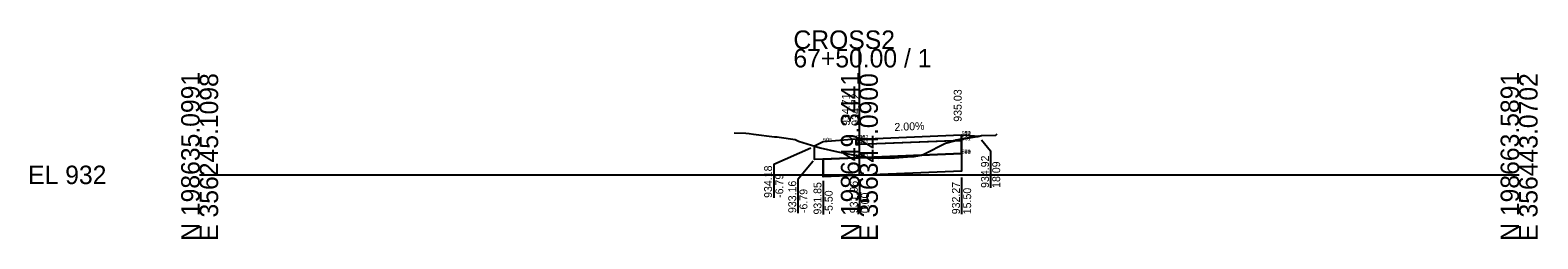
# Model space of a CAD drawing. Extents: x -26 to 203, y -10 to 14021.
# Drawn here: x -25.7 to 202.8, y 8490.3 to 8521.9 of the extents above; entities that cross this region are included whole.
import ezdxf

# ---------------------------------------------------------------- set-up
doc = ezdxf.new("R2010")
doc.units = 0
for name, color, linetype in [('Default', 7, 'Continuous'), ('P_E_XS_Ground', 7, 'Continuous'), ('P_XS', 7, 'Continuous'), ('P_XS_Bold', 7, 'Continuous'), ('P_XS_EAR_CommonGrnd', 7, 'Continuous'), ('P_XS_Lane', 7, 'Continuous'), ('P_XS_Rock', 7, 'Continuous')]:
    doc.layers.add(name, color=color, linetype=linetype)

msp = doc.modelspace()

# ---------------------------------------------------------------- linework, layer by layer
at = {"layer": 'Default'}
for p, q in [((100, 8500), (100, 8519.08)), ((0, 8500), (100, 8500)), ((100, 8500), (200, 8500))]:
    msp.add_line(p, q, dxfattribs=at)
at = {"layer": 'P_E_XS_Ground'}
for p, q in [((81.01, 8506.36), (82.8, 8506.3)), ((82.8, 8506.3), (83.28, 8506.29)), ((83.28, 8506.29), (83.94, 8506.16)), ((83.94, 8506.16), (87.15, 8505.77)), ((118.53, 8505.98), (120.68, 8506)), ((120.68, 8506), (120.89, 8506.23)), ((87.15, 8505.77), (87.53, 8505.74)), ((87.53, 8505.74), (87.86, 8505.71)), ((87.86, 8505.71), (90.25, 8505.35)), ((90.25, 8505.35), (90.77, 8505.13)), ((90.77, 8505.13), (94.07, 8504.09)), ((94.07, 8504.09), (96.71, 8503.5)), ((109.89, 8503.19), (113.07, 8504.79)), ((113.07, 8504.79), (114.63, 8505.24)), ((114.63, 8505.24), (117.57, 8505.75)), ((117.57, 8505.75), (117.94, 8505.8)), ((117.94, 8505.8), (118.53, 8505.98)), ((96.71, 8503.5), (100, 8502.85)), ((100, 8502.85), (100.9, 8502.66)), ((100.9, 8502.66), (101.25, 8502.6)), ((101.25, 8502.6), (102.92, 8502.55)), ((102.92, 8502.55), (105.3, 8502.58)), ((105.3, 8502.58), (107.95, 8502.76)), ((107.95, 8502.76), (108.31, 8502.78)), ((108.31, 8502.78), (109.43, 8502.97)), ((109.43, 8502.97), (109.89, 8503.19))]:
    msp.add_line(p, q, dxfattribs=at)
at = {"layer": 'P_XS'}
for p, q in [((115.5, 8506.05), (115.5, 8505.22)), ((93.21, 8502.33), (93.21, 8504.37)), ((99.5, 8505.41), (99.5, 8504.58)), ((99.5, 8504.58), (100, 8504.6)), ((115.5, 8505.22), (100, 8504.6)), ((115.5, 8503.22), (115.5, 8505.22)), ((99.5, 8502.58), (93.21, 8502.33)), ((94.5, 8502.38), (94.5, 8499.71)), ((99.5, 8502.58), (100, 8502.6)), ((115.5, 8503.22), (100, 8502.6)), ((115.5, 8503.22), (115.5, 8500.55)), ((115.5, 8500.55), (94.5, 8499.71))]:
    msp.add_line(p, q, dxfattribs=at)
at = {"layer": 'P_XS_EAR_CommonGrnd'}
for points in [[(100, 8505.43), (115.5, 8506.05), (115.5, 8505.39), (114.63, 8505.24), (114.4, 8505.17), (100, 8504.6), (99.5, 8504.58), (99.5, 8505.41)], [(115.5, 8506.05), (118.09, 8505.84), (117.94, 8505.8), (117.57, 8505.75), (115.5, 8505.39)], [(96.71, 8503.5), (100, 8502.85), (100.9, 8502.66), (101.02, 8502.64), (109.43, 8502.97), (109.89, 8503.19), (113.07, 8504.79), (114.4, 8505.17), (100, 8504.6), (99.5, 8504.58), (99.5, 8505.41), (94.5, 8505.01), (93.21, 8504.37), (94.07, 8504.09)], [(96.71, 8503.5), (100, 8502.85), (100.9, 8502.66), (101.02, 8502.64), (100, 8502.6), (99.5, 8502.58), (94.5, 8502.38), (93.21, 8502.33), (93.21, 8504.37), (94.07, 8504.09)], [(115.5, 8503.22), (109.43, 8502.97), (109.89, 8503.19), (113.07, 8504.79), (114.4, 8505.17), (115.5, 8505.22)], [(115.5, 8505.22), (114.4, 8505.17), (114.63, 8505.24), (115.5, 8505.39)], [(115.5, 8503.22), (115.5, 8500.55), (94.5, 8499.71), (94.5, 8502.38), (99.5, 8502.58), (100, 8502.6), (101.02, 8502.64), (101.25, 8502.6), (102.92, 8502.55), (105.3, 8502.58), (107.95, 8502.76), (108.31, 8502.78), (109.43, 8502.97)], [(109.43, 8502.97), (101.02, 8502.64), (101.25, 8502.6), (102.92, 8502.55), (105.3, 8502.58), (107.95, 8502.76), (108.31, 8502.78)]]:
    msp.add_lwpolyline(points, close=True, dxfattribs=at)
at = {"layer": 'P_XS_Lane'}
for p, q in [((100, 8505.43), (115.5, 8506.05)), ((115.5, 8506.05), (118.09, 8505.84)), ((94.5, 8505.01), (93.21, 8504.37)), ((99.5, 8505.41), (94.5, 8505.01)), ((99.5, 8505.41), (100, 8505.43))]:
    msp.add_line(p, q, dxfattribs=at)
at = {"layer": 'P_XS_Rock'}
for p, q in [((87.01, 8501.61), (92.66, 8504.12)), ((118.52, 8505.31), (119.89, 8503.63)), ((87.01, 8501.61), (87.01, 8496.51)), ((93.01, 8502.09), (90.67, 8499.31)), ((119.89, 8503.63), (119.89, 8498.01)), ((90.67, 8499.31), (90.67, 8494.21)), ((100, 8499.31), (100, 8494.19)), ((115.49, 8499.62), (115.49, 8494.03)), ((94.5, 8499.1), (94.5, 8493.99))]:
    msp.add_line(p, q, dxfattribs=at)

# ---------------------------------------------------------------- texts
at = {"layer": 'Default'}
for s, p in [('CROSS2', (90, 8519.08)), ('67+50.00 / 1', (90, 8516.28)), ('EL 932', (-26, 8498.6))]:
    msp.add_text(s, height=2.8, dxfattribs=at).set_placement(p)
for s, p in [('N 198635.0991', (0, 8490)), ('E 356245.1098', (2.8, 8490)), ('N 198649.3441', (100, 8490)), ('E 356344.0900', (102.8, 8490)), ('N 198663.5891', (200, 8490)), ('E 356443.0702', (202.8, 8490))]:
    msp.add_text(s, height=2.8, rotation=90, dxfattribs=at).set_placement(p)
at = {"layer": 'P_XS_Bold'}
for s, p in [('951', (99.5, 8505.41)), ('9', (99.5, 8505.41)), ('900', (99.5, 8505.41)), ('952', (100, 8505.43)), ('952', (100, 8505.43)), ('951', (115.5, 8506.05)), ('9', (115.5, 8506.05)), ('900', (115.5, 8506.05)), ('910', (115.5, 8506.05)), ('505', (94.5, 8505.01)), ('961', (99.5, 8504.58)), ('962', (100, 8504.6)), ('962', (100, 8504.6)), ('540', (115.5, 8503.22)), ('961', (115.5, 8505.22)), ('971', (115.5, 8503.22)), ('998', (115.5, 8503.22)), ('971', (99.5, 8502.58)), ('998', (99.5, 8502.58)), ('972', (100, 8502.6)), ('972', (100, 8502.6))]:
    msp.add_text(s, height=0.6, dxfattribs=at).set_placement(p)
at = {"layer": 'P_XS_Rock'}
for s, rotation, p in [('935.03', 90, (115.5, 8508.05)), ('934.71', 90, (98.54, 8507.42)), ('934.72', 90, (100, 8507.43)), ('934.72', 90, (100, 8507.43)), ('934.72', 90, (100, 8507.43)), ('934.72', 90, (100, 8507.43)), ('2.00%', 2.2906, (105.34, 8506.65)), ('934.92', 90, (119.64, 8498.02)), ('18.09', 90, (121.34, 8498.02)), ('934.18', 90, (86.76, 8496.51)), ('-6.79', 90, (88.46, 8496.51)), ('933.16', 90, (90.42, 8494.21)), ('-6.79', 90, (92.12, 8494.21)), ('931.85', 90, (94.25, 8493.99)), ('-5.50', 90, (95.95, 8493.99)), ('931.96', 90, (99.75, 8494.19)), ('0.00', 90, (101.45, 8494.19)), ('932.27', 90, (115.24, 8494.03)), ('15.50', 90, (116.94, 8494.03))]:
    msp.add_text(s, height=1.2, rotation=rotation, dxfattribs=at).set_placement(p)

doc.saveas('drawing.dxf')
